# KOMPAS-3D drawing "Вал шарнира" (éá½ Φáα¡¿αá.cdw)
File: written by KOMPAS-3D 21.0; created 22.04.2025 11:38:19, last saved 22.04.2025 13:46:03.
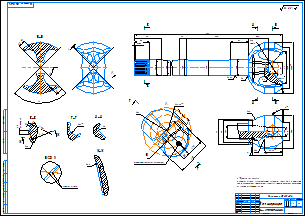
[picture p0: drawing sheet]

Sheet 1: A1, landscape

Document properties: Полное имя файла: Вал шарнира.m3d; Автор: adm; Масса: 9.069085

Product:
- Part/product: Вал шарнира
    Материал: Сталь 27ХГР ГОСТ 4543-2016 (density 7850 kg/m3)
    Масса: 9.069085
    Форматы листов документа: A2
  - Body: Поверхность 7
      Материал: Сталь 27ХГР ГОСТ 4543-2016 (density 0 kg/m3)
  - Body: Поверхность 10
      Материал: Сталь 27ХГР ГОСТ 4543-2016 (density 0 kg/m3)

Title block, sheet 1: Наименование: Вал шарнира; designation: Участник №413-06; Материал: Сталь 27ХГР ГОСТ 4543-2016; Масса: 9,1; Количество листов документа: 1; Форматы листов документа: A1; stored path: C:\Users\USG_413.STUD\Desktop\Вал шарнира.cdw

Views: Вид 1, Местный разрез 1, Спереди, Разрез А-А, Проекционный вид 4, Разрез В-В, Выносной элемент 7, Разрез Д-Д, Разрез Е-Е, Разрез Ж-Ж, Вид по стрелке А, Разрез Г-Г, Выносной элемент Б, Выносной элемент
Referenced files in C:\Users\USG_413.STUD\Desktop\: вал шарнира.m3d
Referenced files in D:\OLIMPGM-2025№1\Г-413\413-06\: Вал шарнира.m3d
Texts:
  сфера
  Ra 1,6
  Ra 6,3 ( )
  Острые кромки
  Поверхности
Dimensions and other numbers on the sheet: 142; 112; 89; 30; 35; 6; 75; 610; 54,5; 173; 50; 18; 74; 42; 45; 44,5; 5; 3; 4; 20; 62; 68; 25; 14; 92,5; 84; 36; 50,38; 2; 50,67; 4,1; 16 шлицев; 41,8; 39,2; 0,5; 1:1; 1; 9,1

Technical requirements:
  *Размеры для справок.
  Острые кромки обеспечиваются радиусом ручья R20 и сферой
  ∅35. Максимальные отклонения размеров от номинальных значений
  не должны превышать 0,1 мм.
